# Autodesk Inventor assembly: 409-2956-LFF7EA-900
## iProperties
Created: 2010-09
Part Number: 409-2956-LFF7EA-900
Document SubType Name: Assembly
Designer: S. Boerckel
Mass: 2.79975e+06 g
Surface Area: 775130 cm^2
Volume: 373059 cm^3
Density: 7.50484 g/cm^3
Description: GENERAL ARRANGEMENT
Material: ASSEMBLY
SMR: =<MATERIAL>
Author: S. Boerckel
Revision Number: 0
